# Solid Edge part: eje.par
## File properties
Author: there
Template: iso metric part.par
Last saved by: there
Revision: 6
Application: Solid Edge
Precisión: 0.990
Username: there
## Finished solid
Body 1: solid body, 3 faces, 2 edges, 0 vertices.
  Faces by surface: plane 2, cylinder 1
  Edges by curve: circle 2
Bounding box of the edges (mm): 6.400 x 80.000 x 6.400, from (-3.2, 0, -3.2) to (3.2, 80, 3.2).
Cylindrical faces by radius (mm): R3.2 x1
Planar faces by outward normal: +y 1, -y 1
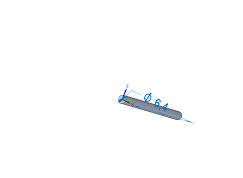
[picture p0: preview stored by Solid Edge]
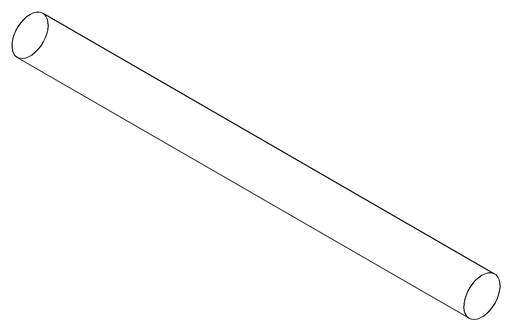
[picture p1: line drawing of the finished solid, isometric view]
